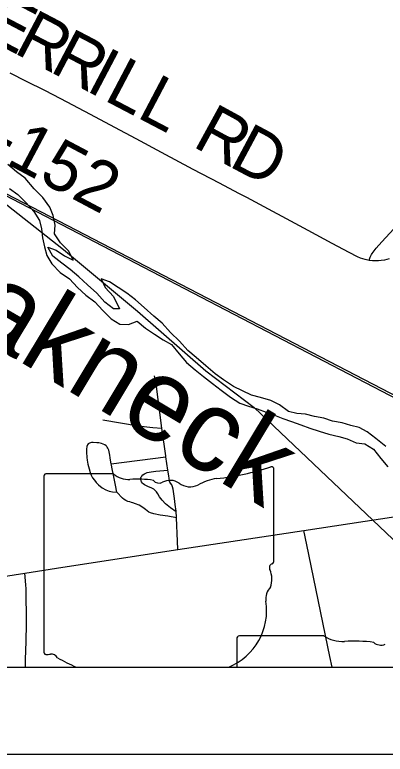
# Model space of a CAD drawing. Extents: x 0 to 34, y 0 to 22.
# Drawn here: x 3.607 to 4.032, y 13.717 to 14.566 of the extents above; entities that cross this region are included whole.
import ezdxf

# ---------------------------------------------------------------- set-up
doc = ezdxf.new("R2010")
doc.units = 0
for name, color, linetype in [('Default', 7, 'Continuous'), ('GM_X_Corporation', 7, 'Continuous'), ('GM_X_Minor_River', 7, 'Continuous'), ('GM_X_Minor_River_Text', 7, 'Continuous'), ('GM_X_Rail_Line', 7, 'Continuous'), ('GM_X_State_Location', 7, 'Continuous'), ('GM_X_State_Route', 7, 'Continuous'), ('GM_X_Township_Road', 7, 'Continuous'), ('GM_X_Township_Road_Text', 7, 'Continuous'), ('SH_Data', 7, 'Continuous')]:
    doc.layers.add(name, color=color, linetype=linetype)

msp = doc.modelspace()

# ---------------------------------------------------------------- linework, layer by layer
at = {"layer": 'Default'}
for p, q in [((3.72025, 14.0388), (3.64297, 14.0388)), ((3.64043, 14.03532), (3.64043, 13.83525)), ((3.96131, 13.85296), (3.86472, 13.85296)), ((3.67774, 13.81727), (3.85247, 13.81727))]:
    msp.add_line(p, q, dxfattribs=at)
for points in [[(3.90408, 13.93909), (3.90407, 13.93909), (3.9041, 13.93907), (3.9041, 14.04394)], [(3.86154, 13.84949), (3.86154, 13.81727), (4.19112, 13.81727), (4.19112, 13.8581)]]:
    msp.add_lwpolyline(points, dxfattribs=at)
for centre, radius, start, end in [((3.64345, 14.03578), 0.00305, 98.97798, 188.59666), ((3.73863, 14.06203), 0.02963, 231.64044, 271.11173), ((3.81018, 14.31163), 0.27962, 275.84447, 288.90645), ((3.90117, 14.04419), 0.00294, 355.09784, 97.73796), ((3.74846, 13.92645), 0.10636, 80.48669, 94.98831), ((3.7726, 14.03682), 0.00855, 219.79206, 297.10237), ((3.78515, 14.01369), 0.01777, 54.46671, 119.14113), ((3.84584, 13.97767), 0.05625, 97.3462, 120.76885), ((3.80809, 14.04541), 0.02138, 233.85619, 294.82819), ((3.90097, 13.93866), 0.00314, 289.60381, 7.73413), ((3.90342, 13.93138), 0.00454, 107.94398, 210.33697), ((3.87452, 13.91815), 0.02727, 340.03296, 23.64957), ((3.91461, 13.89526), 0.01984, 136.8065, 186.92959), ((3.82584, 13.88194), 0.06994, 292.37973, 8.98584), ((3.64348, 13.83479), 0.00308, 171.49107, 258.30654), ((3.64395, 13.85527), 0.02352, 267.33899, 280.60386), ((3.64876, 13.82369), 0.00848, 29.74838, 93.27175), ((3.75582, 14.00349), 0.20192, 240.41292, 247.25165)]:
    msp.add_arc(centre, radius, start, end, dxfattribs=at)
for centre, major_axis, start_param, end_param in [((3.86531, 13.84995), (0.00382, 0), 1.727492, 3.291633), ((3.98429, 13.87619), (0.03703, 0), 4.042888, 4.731792), ((3.99657, 13.74061), (0.13295, 0), 1.404758, 1.657859), ((4.02675, 13.85098), (0.01068, 0), 3.836095, 5.185415)]:
    msp.add_ellipse(centre, major_axis=major_axis, ratio=0.8, start_param=start_param, end_param=end_param, dxfattribs=at)
at = {"layer": 'GM_X_Corporation'}
msp.add_lwpolyline([(4.73203, 17.21351), (3.72594, 17.21067), (3.5941, 17.2097), (3.48484, 17.20877), (3.05968, 17.20671), (2.64928, 17.21019), (2.59523, 17.20975), (2.15896, 17.20547), (2.11404, 17.20482), (2.11404, 13.81727), (5.05386, 13.81727)], dxfattribs=at)
at = {"layer": 'GM_X_Minor_River'}
for points in [[(4.03247, 14.07033), (4.02104, 14.07935), (4.01114, 14.08723), (4.00164, 14.09209), (3.99216, 14.09429), (3.9823, 14.09725), (3.9713, 14.09944), (3.96144, 14.10277), (3.95045, 14.10458), (3.94021, 14.10754), (3.93036, 14.10822), (3.92088, 14.11042), (3.9106, 14.11793), (3.90072, 14.12316), (3.88858, 14.12648), (3.87835, 14.12905), (3.85783, 14.13913), (3.84642, 14.14663), (3.8369, 14.15376), (3.82623, 14.16278), (3.81518, 14.17256), (3.80566, 14.18045), (3.79611, 14.19099), (3.78582, 14.20115), (3.77627, 14.2117), (3.76637, 14.21996), (3.75532, 14.22974), (3.74541, 14.23839), (3.73551, 14.24627), (3.71573, 14.25902), (3.70624, 14.26273), (3.71086, 14.25253), (3.7204, 14.24236), (3.72705, 14.22804), (3.72051, 14.22833), (3.71061, 14.23584), (3.70107, 14.246), (3.6904, 14.25578), (3.68048, 14.26481), (3.67058, 14.27346), (3.66106, 14.28059), (3.65078, 14.28847), (3.64502, 14.29905), (3.65451, 14.29533), (3.66402, 14.28896), (3.67428, 14.28411), (3.66928, 14.29431), (3.65974, 14.30409), (3.65285, 14.31428), (3.65353, 14.32415), (3.65118, 14.33513), (3.64732, 14.34496), (3.63928, 14.3559), (3.62937, 14.36606), (3.61905, 14.37811), (3.60916, 14.38525), (3.59925, 14.39389)], [(3.60136, 14.36622), (3.61087, 14.35947), (3.62041, 14.34968), (3.62919, 14.33989), (3.6357, 14.3297), (3.63767, 14.31985), (3.63888, 14.30962), (3.64123, 14.2994), (3.64396, 14.28956), (3.64971, 14.27974), (3.65925, 14.26996)], [(3.65925, 14.26996), (3.66991, 14.26245), (3.67906, 14.25266), (3.68859, 14.24401), (3.69887, 14.23613), (3.70803, 14.22634), (3.71757, 14.21655), (3.72746, 14.21056), (3.73768, 14.21026), (3.74749, 14.21413), (3.75701, 14.20586), (3.76729, 14.19911), (3.77718, 14.19274), (3.78668, 14.18713), (3.79547, 14.17657), (3.80387, 14.16678), (3.81378, 14.15813), (3.8233, 14.15062), (3.83396, 14.14236), (3.84386, 14.13485), (3.85452, 14.12697), (3.86517, 14.11985), (3.87504, 14.11651), (3.8849, 14.11355), (3.89515, 14.10984), (3.90464, 14.10612), (3.91451, 14.10241), (3.92437, 14.09907), (3.935, 14.09498), (3.94525, 14.09127), (3.95587, 14.08794), (3.96687, 14.08461), (3.97863, 14.08167), (3.98812, 14.07909), (3.99837, 14.07462), (4.00822, 14.07318), (4.01811, 14.06718), (4.02651, 14.05663), (4.03454, 14.04683)]]:
    msp.add_lwpolyline(points, dxfattribs=at)
at = {"layer": 'GM_X_Rail_Line'}
for points in [[(4.60878, 13.83531), (4.56159, 13.85082), (4.51794, 13.87054), (4.4705, 13.89269), (4.42806, 13.91569), (4.04753, 14.12601), (3.57732, 14.37047), (3.17701, 14.58711), (3.04274, 14.65987)], [(4.60803, 13.8331), (4.56074, 13.84864), (4.51696, 13.86842), (4.46944, 13.8906), (4.42693, 13.91364), (4.04642, 14.12395), (3.57622, 14.36841), (3.17589, 14.58506), (3.04162, 14.65782)], [(3.08634, 14.54716), (3.10413, 14.52486), (3.11991, 14.50949), (3.1737, 14.48963), (3.23031, 14.47529), (3.25659, 14.47436), (3.28422, 14.46858), (3.30694, 14.45661), (3.35097, 14.42715), (3.44687, 14.39723), (3.54767, 14.37281), (3.59796, 14.34744), (3.66323, 14.29634), (3.74771, 14.22568), (3.82598, 14.15716), (3.88165, 14.11514), (4.09326, 13.91373), (4.14646, 13.84199), (4.16207, 13.81727)]]:
    msp.add_lwpolyline(points, dxfattribs=at)
at = {"layer": 'GM_X_State_Route'}
for points in [[(3.93851, 13.97399), (4.04387, 13.99003), (4.06261, 13.99288)], [(3.49396, 13.90521), (3.54266, 13.91293), (3.61882, 13.92499), (3.66216, 13.93196), (3.79421, 13.95205), (3.93851, 13.97399)], [(3.97094, 13.81727), (3.96829, 13.82942), (3.94188, 13.95764), (3.93851, 13.97399)]]:
    msp.add_lwpolyline(points, dxfattribs=at)
at = {"layer": 'GM_X_Township_Road'}
for p, q in [((3.71783, 14.05056), (3.78045, 14.05831)), ((3.61942, 13.81727), (3.61968, 13.82861))]:
    msp.add_line(p, q, dxfattribs=at)
for points in [[(3.6015, 14.49907), (3.62034, 14.48954), (3.64141, 14.47889), (3.6596, 14.46955), (3.69349, 14.45157), (3.72141, 14.43676), (3.74587, 14.42357), (3.77481, 14.40793), (3.81128, 14.38856), (3.84152, 14.37275), (3.86339, 14.36098), (3.87266, 14.35618), (3.943, 14.31854), (3.97067, 14.30351), (3.98986, 14.29314), (3.99938, 14.28833), (4.0028, 14.28679), (4.0058, 14.28576), (4.00811, 14.28516), (4.01026, 14.28473), (4.01308, 14.28421), (4.01711, 14.2837), (4.02071, 14.28361), (4.0238, 14.28369), (4.02691, 14.28394), (4.03109, 14.28458), (4.0364, 14.28589)], [(4.01308, 14.28421), (4.01449, 14.28756), (4.01518, 14.28885), (4.01598, 14.29035), (4.0168, 14.29163), (4.01777, 14.29313), (4.02146, 14.29771), (4.02778, 14.30489), (4.04167, 14.31984)], [(3.79421, 13.95205), (3.79377, 13.96153), (3.79252, 13.98859), (3.79247, 13.98974), (3.79206, 13.99516), (3.79197, 13.99623), (3.79115, 14.00355), (3.79008, 14.01053), (3.7887, 14.02132), (3.78804, 14.02395), (3.78705, 14.02634), (3.78567, 14.02826), (3.78492, 14.02938), (3.78446, 14.03067), (3.78356, 14.03651), (3.78264, 14.04298), (3.78045, 14.05831), (3.7803, 14.0594), (3.7757, 14.09117), (3.76937, 14.14214), (3.76751, 14.15144)], [(3.70825, 14.10076), (3.74866, 14.09407), (3.76533, 14.09195), (3.7757, 14.09117)], [(3.79252, 13.98859), (3.78244, 13.99026), (3.77389, 13.99166), (3.76645, 13.9929), (3.76275, 13.99409), (3.76101, 13.99503), (3.75699, 13.9981), (3.75401, 14.00025), (3.74988, 14.00279), (3.74539, 14.00459), (3.74267, 14.0057), (3.74097, 14.00619), (3.73921, 14.00667), (3.73689, 14.00736), (3.73461, 14.00824), (3.73247, 14.00941), (3.73049, 14.0109), (3.72421, 14.01773), (3.72252, 14.02578), (3.7203, 14.03736), (3.71895, 14.04455), (3.71822, 14.04869), (3.71783, 14.05056), (3.71748, 14.05232), (3.71659, 14.05709), (3.7161, 14.0602), (3.71483, 14.06622), (3.71384, 14.06852), (3.71322, 14.06957), (3.71258, 14.07042), (3.71177, 14.07121), (3.71027, 14.07227), (3.70861, 14.07308), (3.70656, 14.07379), (3.7036, 14.07436), (3.7013, 14.07461), (3.69719, 14.07476), (3.69521, 14.0747), (3.69283, 14.0742), (3.69151, 14.07346), (3.69044, 14.07215), (3.6897, 14.07018), (3.68937, 14.06721), (3.68929, 14.06393), (3.68967, 14.05748), (3.69003, 14.05447), (3.69093, 14.05003), (3.69241, 14.04459), (3.69356, 14.04057), (3.69471, 14.03736), (3.69643, 14.03415), (3.69848, 14.03151), (3.70054, 14.02913), (3.70317, 14.02625), (3.70752, 14.0228), (3.71147, 14.02057), (3.71525, 14.01901), (3.71929, 14.01819), (3.72421, 14.01773)], [(3.79206, 13.99516), (3.78584, 13.99981), (3.78011, 14.00453), (3.77594, 14.00864), (3.7729, 14.01253), (3.77117, 14.01579), (3.76951, 14.01842), (3.76788, 14.02029), (3.76644, 14.02145), (3.76426, 14.02262), (3.7596, 14.02438), (3.75745, 14.02549), (3.75603, 14.02647), (3.75452, 14.02752), (3.75365, 14.02839), (3.75258, 14.02983), (3.75205, 14.0308), (3.75154, 14.03296), (3.75166, 14.03416), (3.75205, 14.03534), (3.75269, 14.0364), (3.75397, 14.03773), (3.75602, 14.0391), (3.7591, 14.04033), (3.76346, 14.0414), (3.7688, 14.04205), (3.78264, 14.04298)], [(3.61968, 13.82861), (3.6198, 13.83364), (3.62049, 13.86447), (3.62054, 13.87032), (3.62058, 13.87541), (3.62033, 13.89942), (3.62012, 13.90745), (3.61994, 13.91116), (3.61959, 13.91622), (3.61882, 13.92499)]]:
    msp.add_lwpolyline(points, dxfattribs=at)
at = {"layer": 'SH_Data'}
for p, q in [((2.11404, 13.81727), (8.91404, 13.81727)), ((2.01404, 13.71727), (9.01404, 13.71727))]:
    msp.add_line(p, q, dxfattribs=at)

# ---------------------------------------------------------------- texts
at = {"layer": 'GM_X_Minor_River_Text'}
msp.add_text('Breakneck', height=0.09474, rotation=328.97393, dxfattribs=at).set_placement((3.37961, 14.3079))
at = {"layer": 'GM_X_State_Location'}
for s in ['s', 'r']:
    msp.add_text(s, height=0.000189, dxfattribs=at).set_placement((3.76929, 13.92199))
msp.add_text('59', height=0.000189, rotation=0.00001, dxfattribs=at).set_placement((3.7216, 13.90821))
at = {"layer": 'GM_X_Township_Road_Text'}
for s, height, rotation, p in [('E', 0.05682, 332.31001, (3.56689, 14.54239)), ('R', 0.05682, 332.32255, (3.60454, 14.52263)), ('R', 0.05682, 332.31781, (3.64586, 14.50095)), ('I', 0.05682, 332.32694, (3.6872, 14.47927)), ('L', 0.05682, 332.31751, (3.70786, 14.46843)), ('L', 0.05682, 332.31751, (3.74549, 14.44869)), ('T-152', 0.056818, 332.02611, (3.53237, 14.42926)), ('R', 0.05682, 331.39764, (3.80947, 14.41526)), ('D', 0.05682, 331.96233, (3.85097, 14.39263))]:
    msp.add_text(s, height=height, rotation=rotation, dxfattribs=at).set_placement(p)

doc.saveas('drawing.dxf')
